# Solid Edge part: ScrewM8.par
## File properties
Title: Vis de fixation diamètre 8
Subject: Robinet tournant
Author: ptcarter
Keywords: Acheté
Comments: Diamètre 8x25/Symbole CHc
Template: NORMAL.PAR
Last saved by: ptcarter
Revision: 42
Application: Solid Edge
Category: Robinet
Manager: BU Mécanique
Company: Intergraph France
Quantité: 2
Accuracy: 0.99
File Size: 0
Number of Sheets: 0
Number of Objects: 0
Document Number: 16
Revision: A
Project Name: Robinet tournant
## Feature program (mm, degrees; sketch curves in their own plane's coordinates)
sketch for "unnamed Protrusion 1" plane through (0, 0, 0) normal (0, -1, 0) x-axis (1, 0, 0)
  circle centre (0, 0) radius 4
extrude "unnamed Protrusion 1" add finite 25 along -normal
sketch for "unnamed Protrusion 2" plane through (0, 0, 0) normal (0, -1, 0) x-axis (1, 0, 0)
  circle centre (0, 0) radius 6.5
extrude "unnamed Protrusion 2" add finite 4 along +normal
fillet "unnamed Round 1"
sketch for "ExtrudedCutout_2" plane through (0, 0, 0) normal (0, 0, 1) x-axis (1, 0, 0)
  line (4.8, -3.7037) -> (1.4142, -0.3179)
  arc centre (0, -1.7321) radius 2 from (1.4142, -0.3179) to (-1.4142, -0.3179) ccw
  line (-1.4142, -0.3179) -> (-4.8, -3.7037)
extrude "ExtrudedCutout_2" cut finite 2 symmetric
pattern "unnamed Pattern 1" of "ExtrudedCutout_2"
extrude "unnamed Cutout 1" cut finite 2 symmetric
chamfer "Chamfer_3" setback 0.5
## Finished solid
Body 1: solid body, 34 faces, 65 edges, 33 vertices.
  Faces by surface: plane 22, cylinder 10, cone 1, torus 1
  Edges by curve: line 28, circle 21, intersection 12, ellipse 4
Bounding box of the edges (mm; curved faces can reach further): 13.000 x 29.000 x 13.000, from (-6.5, -4, -6.5) to (6.5, 25, 6.5).
Cylindrical faces by radius (mm): R2 x8, R4 x1, R6.5 x1
Conical faces (half-angle, radius in mm at the cone's reference point): 45 deg R3.5 x1
Toroidal faces (ring radius, tube radius in mm): R3.5 r3 x1
Planar faces by outward normal: +x 3, +y 2, +z 3, -x 3, -y 4, -z 3, oblique 4
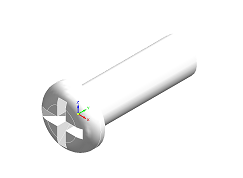
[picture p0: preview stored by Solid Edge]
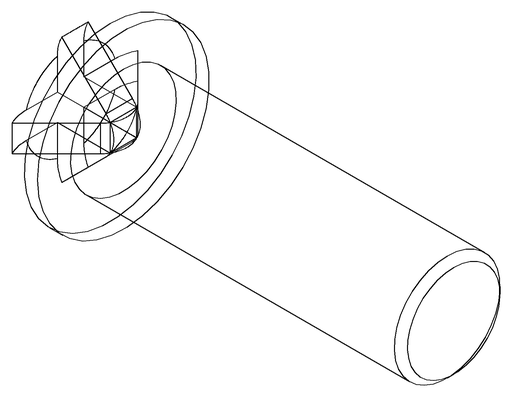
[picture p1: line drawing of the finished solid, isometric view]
